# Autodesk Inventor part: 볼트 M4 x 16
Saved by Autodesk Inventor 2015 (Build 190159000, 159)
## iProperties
Created: 2025-08
Part Number: 볼트 M4 x 16
Material: 일반
Document SubType Name: Modeling
Designer: USER
Density: 1 g/cm^3
Appearance: 기본값
Author: USER
Author: jhkim
Description: 6각 소켓 머리 캡 나사
Creation Date: 2025-08-05
Sending System: Autodesk Inventor 2026
Preprocessor: ST-DEVELOPER v20.1
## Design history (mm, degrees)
node "볼트 M4 x 161"
body "Solid1"
node "기준1"
